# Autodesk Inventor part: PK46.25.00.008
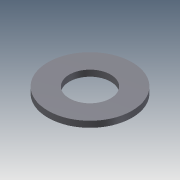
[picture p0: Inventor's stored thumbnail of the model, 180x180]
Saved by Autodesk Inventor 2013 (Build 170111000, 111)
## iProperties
Created: 2005-05
Part Number: PK46.25.00.008
Material: Steel, Mild
Document SubType Name: Modeling
Designer: PVitaliy
Manufacturer: Standard
Standards Organization: Custom
Density: 7.86 g/cm^3
Mass: 453.56 g
Surface Area: 185.48 cm^2
Volume: 57.7048 cm^3
Author: PVitaliy
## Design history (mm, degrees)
sketch "Эскиз2"
  geometry: C1 r 55 at (0, 0); C2 r 27 at (0, 0)
  constraints: 2 centre point, 1 coincident, 1 other
  dimensions: "d0" = 110 diameter of C1; "d1" = 54 diameter of C2
extrude "Выдавливание1" new body sketch "Эскиз2" distance "d2" = 8; taper "d3" = 0 deg
body "Solid1"
